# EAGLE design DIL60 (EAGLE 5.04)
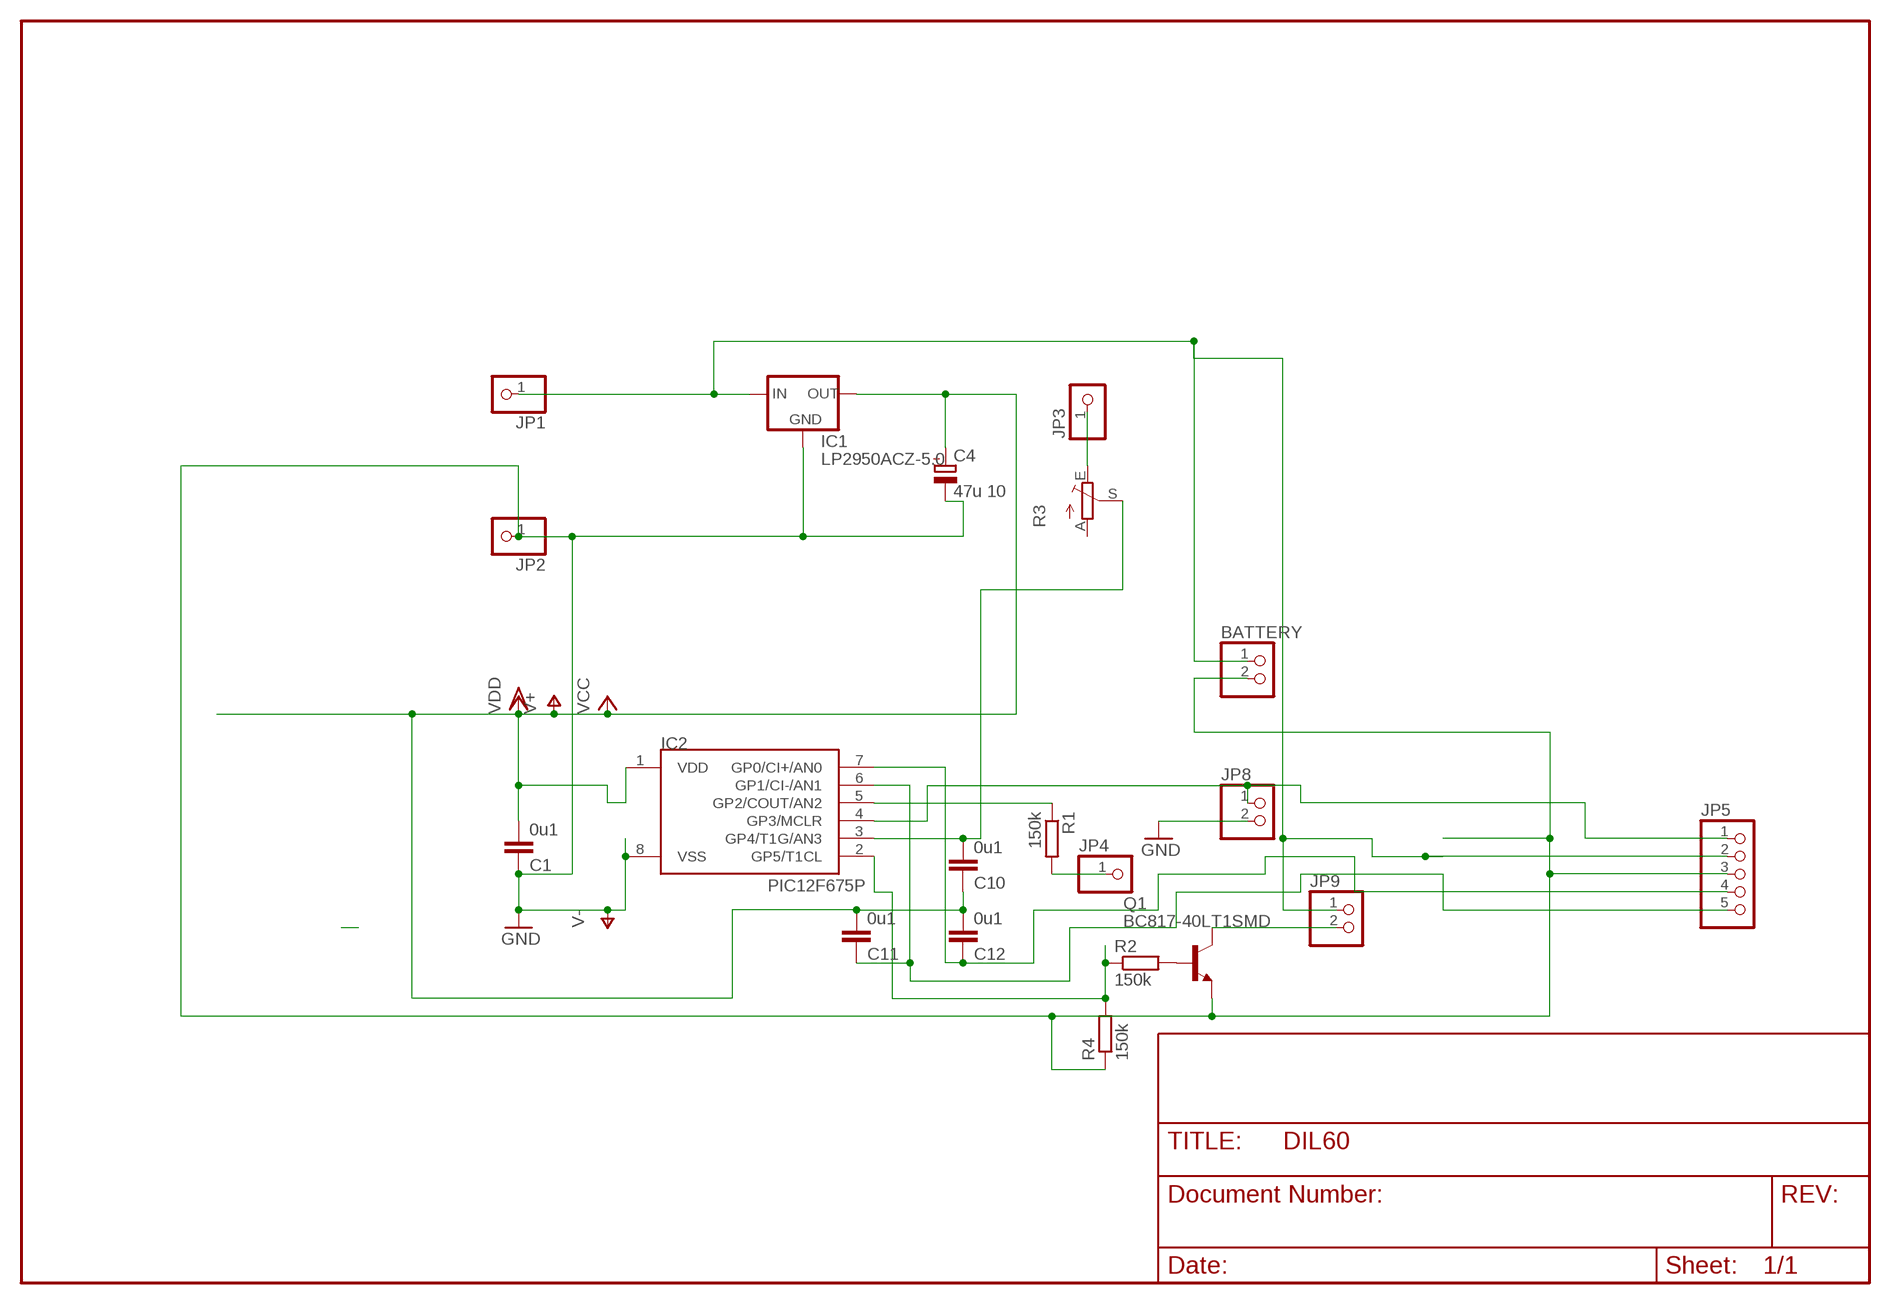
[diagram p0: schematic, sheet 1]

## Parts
BATTERY  PINHD-1X2  [1X02]
C1  0u1  C-EUC1206  [C1206]
C4  47u 10  CPOL-EUE2.5-6  [E2,5-6]
C10  0u1  C-EUC1206  [C1206]
C11  0u1  C-EUC1206  [C1206]
C12  0u1  C-EUC1206  [C1206]
IC1  LP2950ACZ-5.0  [TO92]
IC2  PIC12F675P  [DIL8]
JP1  PINHD-1X1  [1X01]
JP2  PINHD-1X1  [1X01]
JP3  PINHD-1X1  [1X01]
JP4  PINHD-1X1  [1X01]
JP5  PINHD-1X5  [1X05]
JP8  PINHD-1X2  [1X02]
JP9  PINHD-1X2  [1X02]
Q1  BC817-40LT1SMD  [SOT23-BEC]
R1  150k  R-EU_R0805  [R0805]
R2  150k  R-EU_R0805  [R0805]
R3  TRIM_EU-CA6V  [CA6V]
R4  150k  R-EU_R0805  [R0805]

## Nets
GND: BATTERY.2 C1.1 C4.- IC1.2(GND) IC2.8(VSS) JP2.1 JP5.3 JP8.2 Q1.E R4.1 ; supply symbol labelled V-
N$1: JP3.1 R3.E
N$2: JP4.1 R1.2
N$3: IC2.4(GP3/MCLR) JP5.1 JP8.1
N$4: Q1.B R2.2
N$5: IC2.5(GP2/COUT/AN2) R1.1
N$8: IC2.2(GP5/T1CL) R2.1 R4.2
N$9: BATTERY.1 IC1.3(IN) JP1.1 JP5.2 JP9.1
N$12: C10.2 IC2.3(GP4/T1G/AN3) R3.S
N$13: C12.1 IC2.7(GP0/CI+/AN0) JP5.4
N$14: JP9.2 Q1.C
N$15: C11.1 IC2.6(GP1/CI-/AN1) JP5.5
V+: C1.2 C4.+ C10.1 C11.2 C12.2 IC1.1(OUT) IC2.1(VDD) ; supply symbol labelled VDD, VCC
Unconnected: R3.A

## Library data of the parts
BATTERY JP8 JP9 = pinhead:PINHD-1X2: PIN HEADER
C1 C10-C12 = rcl:C-EU: CAPACITOR, European symbol
C4 = rcl:CPOL-EU: POLARIZED CAPACITOR, European symbol
IC1 = v-reg:LP2950?*: Source: http://cache.national.com/ds/LP/LP2950.pdf
IC2 = microchip-3:PIC12F6*: uPC nW 1k Program Flash memory 2x Timer Comparator 10b A/D converter/ 4xIN
JP1-JP4 = pinhead:PINHD-1X1: PIN HEADER
JP5 = pinhead:PINHD-1X5: PIN HEADER
Q1 = transistor-npn:BC817*: NPN Transistor
R1 R2 R4 = rcl:R-EU_: RESISTOR, European symbol
R3 = pot:TRIM_EU-: POTENTIOMETER

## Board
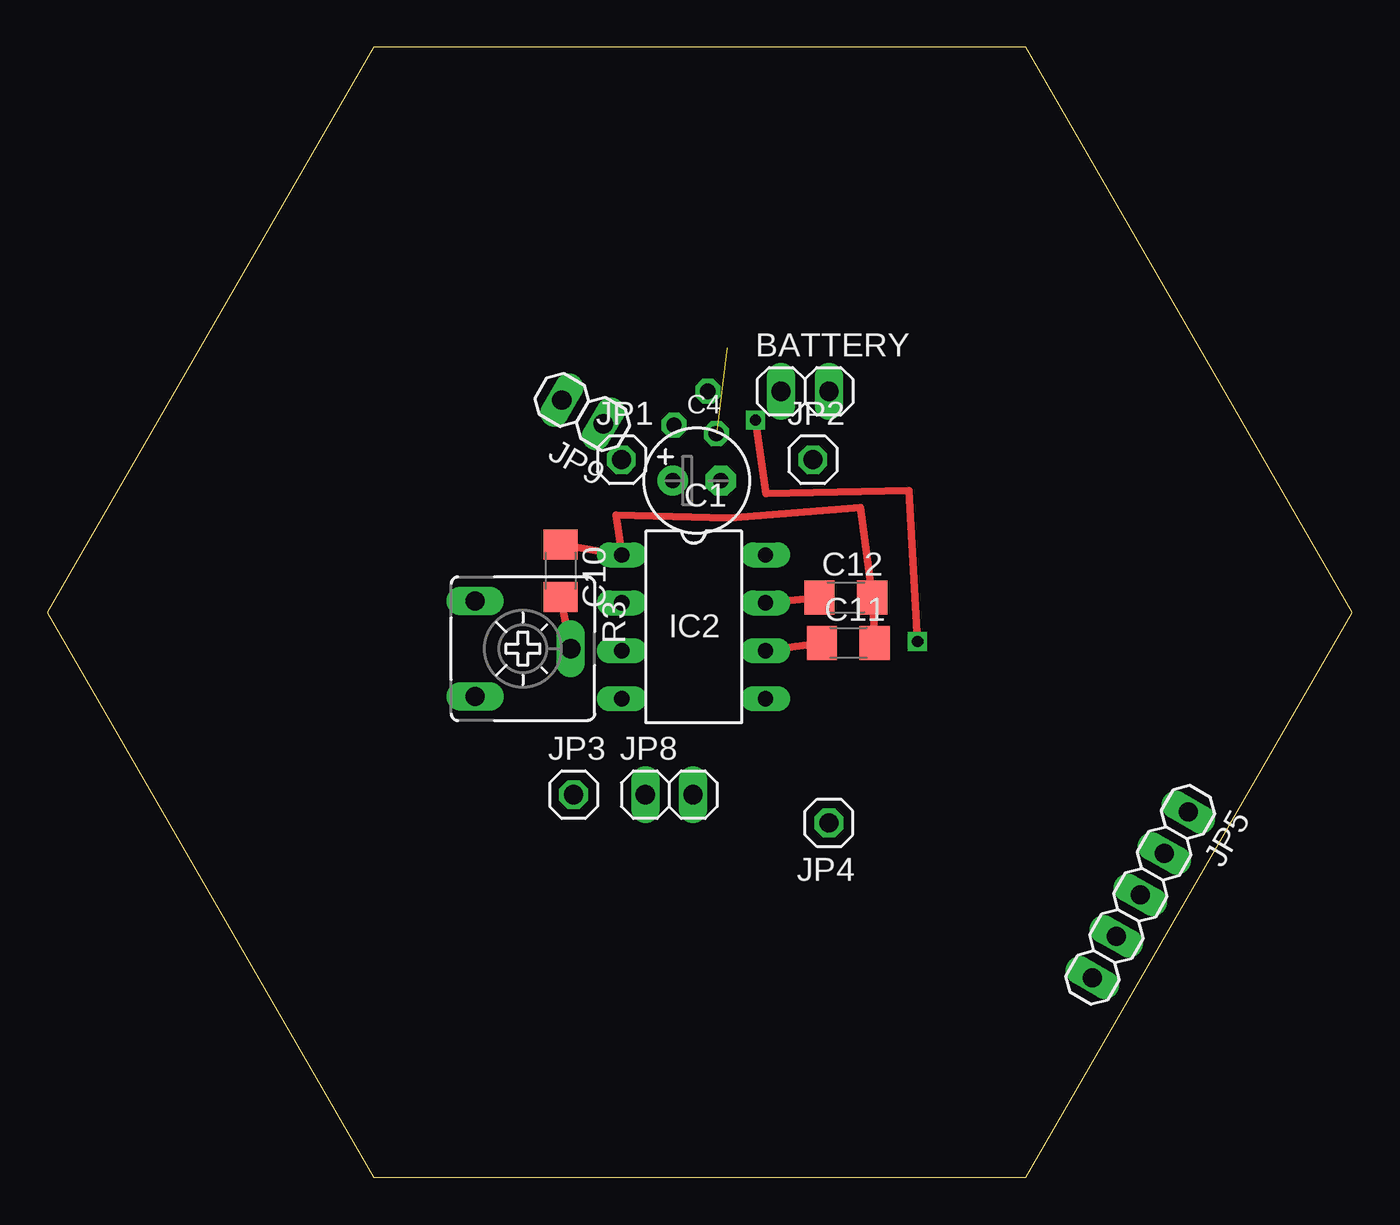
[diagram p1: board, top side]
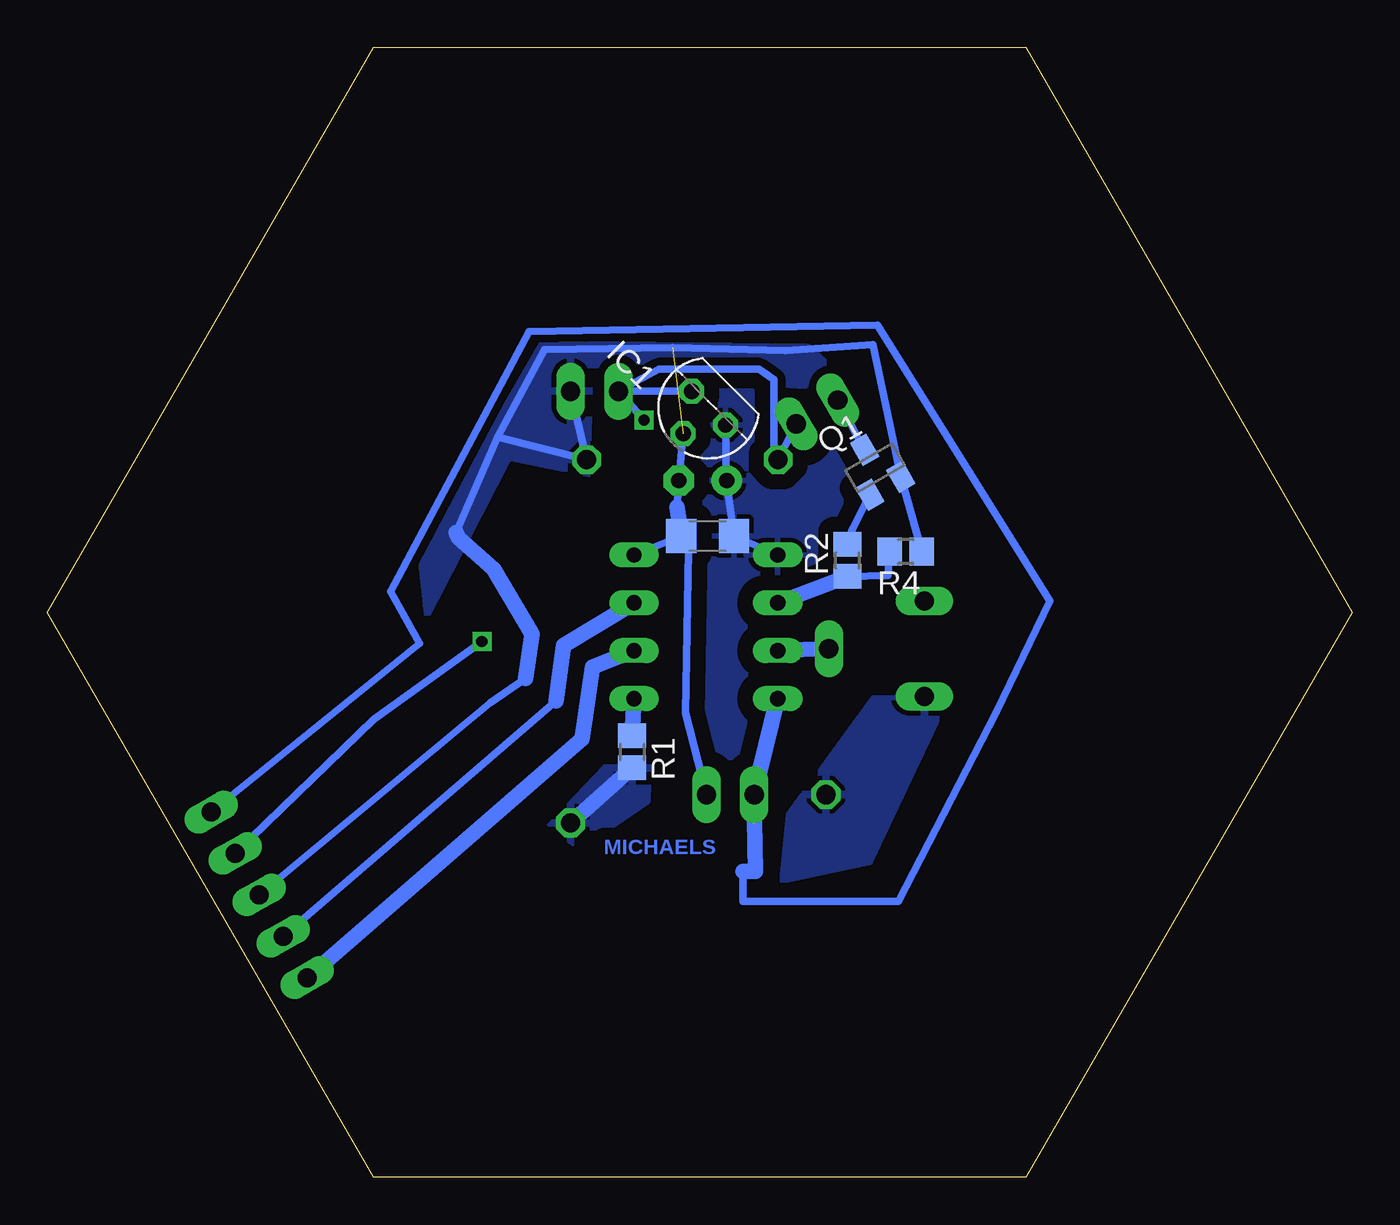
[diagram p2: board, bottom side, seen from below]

Size 69.28 x 60 mm. Coordinates in mm from the lower left corner, seen from the top.
Outline: 17.32,0 51.96,0 69.28,30 51.96,60 17.32,60 0,30 17.32,0
Copper layers (1*16): Top 0.035mm / dielectric 1.5mm / Bottom 0.035mm
Design rules "default *": minimum track width 10mil, minimum drill 24mil, track to track 8mil, track to pad 8mil, pad to pad 8mil, via to via 8mil, smd to smd 8mil, copper to edge 10mil, drill to drill 8mil, minimum pad ring 10mil, minimum via ring 8mil, stop-mask expansion 4mil, vias tented up to drill 0mil, thermal gap 10mil

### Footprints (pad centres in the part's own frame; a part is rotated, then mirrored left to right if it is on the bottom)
1X02 = drill 1.016 long: 1 -1.27,0; 2 1.27,0
C1206 = smd 1.6 x 1.8: 1 -1.4,0; 2 1.4,0
E2,5-6 = drill 0.813 pad 1.6 round: + -1.27,0 | drill 0.813 pad 1.6 octagon: - 1.27,0
TO92 = drill 0.813 octagon: 1 -1.27,0; 2 0,1.905; 3 1.27,0
DIL8 = drill 0.813 long: 1 -3.81,-3.81; 2 -1.27,-3.81; 3 1.27,-3.81; 4 3.81,-3.81; 5 3.81,3.81; 6 1.27,3.81; 7 -1.27,3.81; 8 -3.81,3.81
1X01 = drill 1.016 octagon: 1 0,0
1X05 = drill 1.016 long: 1 -5.08,0; 2 -2.54,0; 3 0,0; 4 2.54,0; 5 5.08,0
SOT23-BEC = smd 1 x 1.4: B -0.95,-1.1; C 0,1.1; E 0.95,-1.1
R0805 = smd 1.3 x 1.5: 1 -0.85,0; 2 0.85,0
CA6V = drill 1.016 long: A -2.54,-2.54; E 2.54,-2.54; S 0,2.54

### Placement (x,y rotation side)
BATTERY  40.22,41.73 0 top
C1  34.22,34.05 0 bottom
C4  34.48,36.99 0 top
C10  27.25,32.2 270 top
C11  42.53,28.38 0 top
C12  42.39,30.78 0 top
IC1  34.17,40.84 135 bottom
IC2  34.32,29.23 270 top
JP1  30.48,38.1 0 top
JP2  40.64,38.1 0 top
JP3  27.94,20.32 0 top
JP4  41.5,18.82 180 top
JP5  58.03,15 240 top
JP8  33.02,20.32 0 top
JP9  28.42,40.64 150 top
Q1  25.34,37.67 30 bottom
R1  38.23,22.59 270 bottom
R2  26.8,32.75 90 bottom
R3  25.25,28.07 270 top
R4  23.71,33.22 180 bottom

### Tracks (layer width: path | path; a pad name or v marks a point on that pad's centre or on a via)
GND  (1 unrouted)
  Bottom 0.406: 35.85,35.59 C4.- IC1.2 | 45.36,39.29 47.58,34.24 | 45.36,39.29 42.88,43.94 36.08,44.04 30.08,43.89 25.45,44.2 Q1.E R4.1 | 45.36,39.29 JP2.1 BATTERY.2 | 43.88,26.49 45.78,25.19 JP5.3 | IC2.8 C1.1 35.25,33.3 35.4,24.65 JP8.2
  Bottom 0.813: C1.1 35.85,35.59 | 47.58,34.24 47.43,33.94 45.58,32.29 43.53,28.84 43.88,26.49
  pour Bottom (isolate 0.406, rank 2): 27.94,43.18 28.88,44.04 42.98,44.24 49.43,33.09 49.08,29.94 44.78,38.24 40.38,37.34 40.58,39.34 40.48,43.14 38.68,43.14 36.88,42.24 35.98,41.09 34.68,41.09 34.78,42.44 29.08,42.04
N$1
  pour Bottom (isolate 0.61): 22.86,25.4 25.4,25.4 29.88,19.24 30.23,15.79 25.63,16.79 21.48,25.59
N$2
  Bottom 0.813: JP4.1 R1.2
  pour Bottom (isolate 0.61): 40.64,17.78 37.43,19.99 37.38,21.89 39.63,21.74 42.63,18.59 41.08,17.64
N$3
  Bottom 0.406: JP5.1 49.5,28.35 51.05,31.1 43.7,44.9 25.2,45.25 16.05,30.6 18.9,24.7 24.1,14.65 32.35,14.65 32.35,16.24
  Bottom 0.813: IC2.4 JP8.1 31.68,16.24 32.35,16.24
N$4
  Bottom 0.406: Q1.B 26.54,34.41 R2.2
N$5
  Bottom 0.813: R1.1 IC2.5
N$8
  Bottom 0.406: R2.1 24.65,31.95 R4.2
  Bottom 0.813: R2.1 IC2.2
N$9  (via drill 0.6)
  Top 0.406: v46.2,28.45 45.75,36.45 38.15,36.3 v37.6,40.2
  Bottom 0.406: BATTERY.1 36.8,42.9 31.5,42.9 30.7,42.35 30.7,38.1 JP1.1 JP9.1 | BATTERY.1 IC1.3 | JP5.2 51.95,24.3 v46.2,28.45 | BATTERY.1 v37.6,40.2
N$12
  Top 0.406: R3.S C10.2
  Bottom 0.813: R3.S IC2.3
N$13
  Top 0.406: IC2.7 C12.1
  Bottom 0.406: 42.28,25.29 JP5.4
  Bottom 0.813: IC2.7 41.88,28.24 42.28,25.29
N$14
  Bottom 0.406: Q1.C JP9.2
N$15
  Top 0.406: IC2.6 C11.1
  Bottom 0.813: IC2.6 40.33,27.09 40.88,23.28 JP5.5
V+
  Top 0.406: C10.1 IC2.1 30.2,35.15 36.2,35 43.18,35.56 C12.2 C11.2
  Bottom 0.406: IC2.1 C1.2 C4.+ IC1.1
  pour Bottom (isolate 0.813, rank 4): 42.87,15.89 24.72,16.09 17.15,29.95 25.72,43.49 41.68,44.22 46.03,39.48 50.92,29.15

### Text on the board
Bottom: MICHAELS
